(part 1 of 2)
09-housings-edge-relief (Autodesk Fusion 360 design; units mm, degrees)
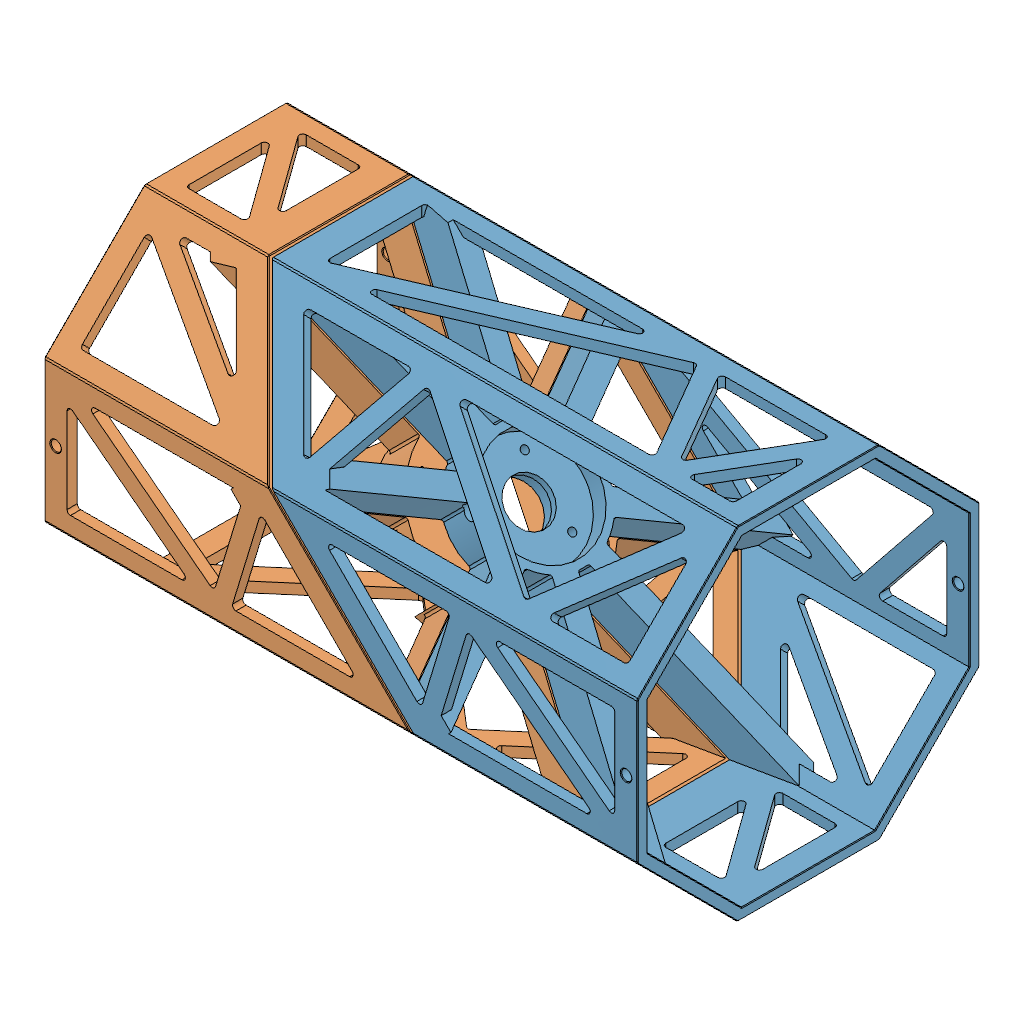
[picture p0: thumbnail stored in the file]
part number: 2026-11-02-20-17-55-344
part number: 2026-11-02-20-17-59-218
part number: 2026-11-02-20-17-59-224
parameter "bodyWidth" = 150 comment "Regular octagon across flats; corner diameter is larger."
parameter "bodyLength" = 260 comment "Overall straight length of the shared master blank."
parameter "splitAngle" = 45 comment "Keep this lesson angle at45 degrees."
parameter "faceGap" = 1 comment "Gap between the two printed joint faces."
parameter "wall" = 4.5 comment "Integrated shell and side brace radial thickness."
parameter "faceHalfWidth" = 31.066 (= "bodyWidth * ( sqrt(2) - 1 ) / 2") comment "Half-width of each outer planar facet."
parameter "memberWidth" = 8 comment "Nominal brace and corner chord width in a facet."
parameter "nodeHalfWidth" = 27.066 (= "faceHalfWidth - memberWidth / 2") comment "Chord centerlines measured from facet center."
parameter "jointNodeQ" = 7 comment "First truss skeleton row from the center joint plane."
parameter "endRim" = 10 comment "Uncut axial rim at each distant end."
parameter "endNodeX" = 124 (= "bodyLength / 2 - endRim + memberWidth / 2") comment "Last skeleton row before aperture inset."
parameter "apertureRadius" = 1.5 comment "Rounded internal corners at triangular openings."
parameter "spokeWidth" = 10 comment "Width of each deep bearing bulkhead spoke."
parameter "spokeDepth" = 18 comment "Bulkhead depth normal to the diagonal joint face."
parameter "carrierOD" = 52 comment "Outside of integrated A front bearing carrier."
parameter "rearCarrierClearance" = 46 comment "Internal carrier relief above front bearing shoulder."
parameter "tubeCornerChamfer" = 0.5 comment "Exposed outside octagon corner bevel."
parameter "tubeRimChamfer" = 0.3 comment "End rim and print-contact edge relief."
parameter "cordStation" = 125 (= "bodyLength / 2 - endRim / 2") comment "Load-test cord port center measured along body X."
parameter "bearingOD" = 22 comment "608 measured outside diameter."
parameter "bearingID" = 8 comment "608 bore."
parameter "bearingWidth" = 7 comment "608 width."
parameter "seatAllowance" = 0.2 comment "Trial DIAMETRAL clearance; choose with printed coupon."
parameter "seatDiameter" = 22.2 (= "bearingOD + seatAllowance") comment "Measured fit controls this."
parameter "coreOD" = 44 comment "Bearing holder outer diameter."
parameter "raceRelief" = 19.5 comment "Outer-ring shoulder opening; verify seals."
parameter "frontSeatDepth" = 7.1 comment "0.1 mm outer-ring axial allowance."
parameter "rearSeatDepth" = 7.2 comment "0.2 mm outer-ring axial float."
parameter "shoulder" = 3 comment "Backing behind each bearing seat."
parameter "supportSpacer" = 12 comment "Purchased metal M3 spacer length."
parameter "supportCircle" = 34 comment "Three M3 support bolts."
parameter "supportSpacerOD" = 6 comment "Purchased spacer outside diameter."
parameter "capThickness" = 3 comment "Both printed outer-ring retaining caps."
parameter "m3Clearance" = 3.3 comment "M3 through holes."
parameter "m4Clearance" = 4.3 comment "M4 through holes."
parameter "qFront" = 0.5 (= "faceGap / 2") comment "Front bearing starts at A mating face."
parameter "qFrontBack" = 10.6 (= "qFront + frontSeatDepth + shoulder") comment "End of integrated A holder."
parameter "qRearBase" = 22.6 (= "qFrontBack + supportSpacer") comment "Start of removable rear holder."
parameter "qRearBearing" = 25.6 (= "qRearBase + shoulder") comment "Rear bearing inner end."
parameter "qRearEnd" = 32.8 (= "qRearBearing + rearSeatDepth") comment "Rear holder outer end."
parameter "bearingSpacing" = 25.1 (= "qRearBearing - qFront") comment "Derived support-center spacing, not a bearing rating."
parameter "mountOD" = 76 comment "B mount and F flange outside diameter."
parameter "mountCircle" = 64 comment "Four M4 attachment holes."
parameter "mountOpening" = 50.3 comment "B through opening."
parameter "hubFace" = -23 comment "Metal hub flat mounting face."
parameter "adapterThickness" = 6 comment "F flange and metal compression sleeve length."
parameter "pilotDiameter" = 50 comment "F shallow centering pilot."
parameter "pilotInside" = 34 comment "Clearance around metal hub."
parameter "pilotHeight" = 2 comment "Short pilot only."
parameter "hubHoleSpacing" = 16 comment "Metal Sonic hub square hole spacing."
parameter "sleeveOD" = 8 comment "M4 metal compression sleeves."
parameter "sleeveAllowance" = 0.2 comment "Trial DIAMETRAL sleeve clearance."
parameter "shaftClearance" = 8.5 comment "F clearance hole; not a bearing."
parameter "nutAF" = 7.2 comment "M4 nominal 7 AF nut trial pocket."
parameter "nutDepth" = 4 comment "Open front M4 nut pocket."
parameter "rootRadius" = 1 comment "Hub-to-wall blend."
parameter "entryChamfer" = 0.4 comment "Assembly lead-in."
parameter "bedRelief" = 0.3 comment "Bed-contact edge allowance."
sketch "01 Master Octagon" plane through (0, 0, 0) normal (1, 0, 0) x axis (0, 0, -1)
  line L1 (31.066, 75) -> (75, 31.066)
  line L2 (-31.066, 75) -> (31.066, 75)
  line L3 (-75, 31.066) -> (-31.066, 75)
  line L4 (-75, -31.066) -> (-75, 31.066)
  line L5 (-31.066, -75) -> (-75, -31.066)
  line L6 (31.066, -75) -> (-31.066, -75)
  line L7 (75, -31.066) -> (31.066, -75)
  line L8 (75, 31.066) -> (75, -31.066)
  point P1 (0, 0)
  point P10 (0, 0)
  point P3 (31.066, 75)
  point P8 (31.066, -75)
  coincident P1 P10
  horizontal L2
  dimension "d59" distance P3 P8 = 150 (= "bodyWidth")
extrude "Extrude1" new body sketch "01 Master Octagon" distance 260 (= "bodyLength")
work_plane "WorkPlane1" RotateAngle 45 (= "splitAngle") ExtraOffset 0
split "Split1"
offset_faces "OffsetFaces1" distance -0.5 (= "-faceGap / 2")
offset_faces "OffsetFaces2" distance -0.5 (= "-faceGap / 2")
component_from_bodies "Body->Comp1"
component_from_bodies "Body->Comp2"
shell "Shell1" innerThickness 4.5 (= "wall")
shell "Shell1" innerThickness 4.5 (= "wall")
work_plane "WorkPlane1" RotateAngle -90 ExtraOffset 0
work_plane "WorkPlane2" AlongDistance 75 (= "bodyWidth / 2") ExtraOffset 0
sketch "A Facet 0 Triangle 1" plane through (0, 75, 0) normal (0, 1, 0) x axis (1, 0, 0)
  line L1 (-65.1005, -27.066) -> (-65.1005, 27.066)
  line L2 (60.9665, 27.066) -> (-65.1005, -27.066)
  line L3 (-65.1005, 27.066) -> (60.9665, 27.066)
  line L4 (-61.1005, -20.9953) -> (-61.1005, 23.066)
  line L5 (41.513, 23.066) -> (-61.1005, -20.9953)
  line L6 (-61.1005, 23.066) -> (41.513, 23.066)
  point P1 (0, 0)
  point P2 (-65.1005, 27.066)
  point P3 (-65.1005, -27.066)
  point P4 (60.9665, 27.066)
  dimension "d72" distance P1 P2 = 65.1005 (= "Linear Dimension-2")
  dimension "d73" distance P1 P2 = 27.066 (= "Linear Dimension-3")
  dimension "d74" distance P1 P3 = 65.1005 (= "Linear Dimension-4")
  dimension "d75" distance P1 P3 = 27.066 (= "Linear Dimension-5")
  dimension "d76" distance P1 P4 = 60.9665 (= "Linear Dimension-6")
  dimension "d77" distance P1 P4 = 27.066 (= "Linear Dimension-7")
  dimension "d78" = -4 (= "-memberWidth / 2")
extrude "Extrude1" cut sketch "A Facet 0 Triangle 1" profile of L5 L6 L4 against normal blind 4.7 (magnitude of "-( wall + 0.2 mm )")
sketch "A Facet 0 Triangle 2" plane through (0, 75, 0) normal (0, 1, 0) x axis (1, 0, 0)
  line L1 (60.9665, 27.066) -> (-65.1005, -27.066)
  line L2 (92.4832, -27.066) -> (60.9665, 27.066)
  line L3 (-65.1005, -27.066) -> (92.4832, -27.066)
  line L4 (59.2912, 21.9935) -> (-45.647, -23.066)
  line L5 (85.5258, -23.066) -> (59.2912, 21.9935)
  line L6 (-45.647, -23.066) -> (85.5258, -23.066)
  point P1 (0, 0)
  point P2 (-65.1005, -27.066)
  point P3 (60.9665, 27.066)
  point P4 (92.4832, -27.066)
  dimension "d81" distance P1 P2 = 65.1005 (= "Linear Dimension-2")
  dimension "d82" distance P1 P2 = 27.066 (= "Linear Dimension-3")
  dimension "d83" distance P1 P3 = 60.9665 (= "Linear Dimension-4")
  dimension "d84" distance P1 P3 = 27.066 (= "Linear Dimension-5")
  dimension "d85" distance P1 P4 = 92.4832 (= "Linear Dimension-6")
  dimension "d86" distance P1 P4 = 27.066 (= "Linear Dimension-7")
  dimension "d87" = 4 (= "memberWidth / 2")
extrude "Extrude2" cut sketch "A Facet 0 Triangle 2" profile of L5 L6 L4 against normal blind 4.7 (magnitude of "-( wall + 0.2 mm )")
sketch "A Facet 0 Triangle 3" plane through (0, 75, 0) normal (0, 1, 0) x axis (1, 0, 0)
  line L1 (92.4832, -27.066) -> (60.9665, 27.066)
  line L2 (124, 27.066) -> (92.4832, -27.066)
  line L3 (60.9665, 27.066) -> (124, 27.066)
  line L4 (92.4832, -19.1161) -> (67.924, 23.066)
  line L5 (117.0425, 23.066) -> (92.4832, -19.1161)
  line L6 (67.924, 23.066) -> (117.0425, 23.066)
  point P1 (0, 0)
  point P2 (60.9665, 27.066)
  point P3 (92.4832, -27.066)
  point P4 (124, 27.066)
  dimension "d90" distance P1 P2 = 60.9665 (= "Linear Dimension-2")
  dimension "d91" distance P1 P2 = 27.066 (= "Linear Dimension-3")
  dimension "d92" distance P1 P3 = 92.4832 (= "Linear Dimension-4")
  dimension "d93" distance P1 P3 = 27.066 (= "Linear Dimension-5")
  dimension "d94" distance P1 P4 = 124 (= "Linear Dimension-6")
  dimension "d95" distance P1 P4 = 27.066 (= "Linear Dimension-7")
  dimension "d96" = -4 (= "-memberWidth / 2")
extrude "Extrude3" cut sketch "A Facet 0 Triangle 3" profile of L5 L6 L4 against normal blind 4.7 (magnitude of "-( wall + 0.2 mm )")
sketch "A Facet 0 Triangle 4" plane through (0, 75, 0) normal (0, 1, 0) x axis (1, 0, 0)
  line L1 (124, 27.066) -> (92.4832, -27.066)
  line L2 (124, -27.066) -> (124, 27.066)
  line L3 (92.4832, -27.066) -> (124, -27.066)
  line L4 (120, 12.2459) -> (99.4407, -23.066)
  line L5 (120, -23.066) -> (120, 12.2459)
  line L6 (99.4407, -23.066) -> (120, -23.066)
  point P1 (0, 0)
  point P2 (92.4832, -27.066)
  point P3 (124, 27.066)
  point P4 (124, -27.066)
  dimension "d99" distance P1 P2 = 92.4832 (= "Linear Dimension-2")
  dimension "d100" distance P1 P2 = 27.066 (= "Linear Dimension-3")
  dimension "d101" distance P1 P3 = 124 (= "Linear Dimension-4")
  dimension "d102" distance P1 P3 = 27.066 (= "Linear Dimension-5")
  dimension "d103" distance P1 P4 = 124 (= "Linear Dimension-6")
  dimension "d104" distance P1 P4 = 27.066 (= "Linear Dimension-7")
  dimension "d105" = 4 (= "memberWidth / 2")
extrude "Extrude4" cut sketch "A Facet 0 Triangle 4" profile of L5 L6 L4 against normal blind 4.7 (magnitude of "-( wall + 0.2 mm )")
fillet "Fillet1" radius 1.5 (= "apertureRadius")
work_plane "WorkPlane3" RotateAngle -45 ExtraOffset 0
work_plane "WorkPlane4" AlongDistance 75 (= "bodyWidth / 2") ExtraOffset 0
sketch "A Facet 45 Triangle 1" plane through (0, 53.033, 53.033) normal (0, 0.7071, 0.7071) x axis (1, 0, 0)
  line L1 (-23.9949, -27.066) -> (-62.2721, 27.066)
  line L2 (-0.1814, 27.066) -> (-23.9949, -27.066)
  line L3 (-62.2721, 27.066) -> (-0.1814, 27.066)
  line L4 (-24.81, -18.9852) -> (-54.5447, 23.066)
  line L5 (-6.311, 23.066) -> (-24.81, -18.9852)
  line L6 (-54.5447, 23.066) -> (-6.311, 23.066)
  point P1 (0, 0)
  point P2 (-62.2721, 27.066)
  point P3 (-23.9949, -27.066)
  point P4 (-0.1814, 27.066)
  dimension "d114" distance P1 P2 = 62.2721 (= "Linear Dimension-2")
  dimension "d115" distance P1 P2 = 27.066 (= "Linear Dimension-3")
  dimension "d116" distance P1 P3 = 23.9949 (= "Linear Dimension-4")
  dimension "d117" distance P1 P3 = 27.066 (= "Linear Dimension-5")
  dimension "d118" distance P1 P4 = 0.1814 (= "Linear Dimension-6")
  dimension "d119" distance P1 P4 = 27.066 (= "Linear Dimension-7")
  dimension "d120" = -4 (= "-memberWidth / 2")
extrude "Extrude5" cut sketch "A Facet 45 Triangle 1" profile of L5 L6 L4 against normal blind 4.7 (magnitude of "-( wall + 0.2 mm )")
sketch "A Facet 45 Triangle 2" plane through (0, 53.033, 53.033) normal (0, 0.7071, 0.7071) x axis (1, 0, 0)
  line L1 (-0.1814, 27.066) -> (-23.9949, -27.066)
  line L2 (74.6684, -27.066) -> (-0.1814, 27.066)
  line L3 (-23.9949, -27.066) -> (74.6684, -27.066)
  line L4 (1.4863, 20.9235) -> (-17.8653, -23.066)
  line L5 (62.3117, -23.066) -> (1.4863, 20.9235)
  line L6 (-17.8653, -23.066) -> (62.3117, -23.066)
  point P1 (0, 0)
  point P2 (-23.9949, -27.066)
  point P3 (-0.1814, 27.066)
  point P4 (74.6684, -27.066)
  dimension "d123" distance P1 P2 = 23.9949 (= "Linear Dimension-2")
  dimension "d124" distance P1 P2 = 27.066 (= "Linear Dimension-3")
  dimension "d125" distance P1 P3 = 0.1814 (= "Linear Dimension-4")
  dimension "d126" distance P1 P3 = 27.066 (= "Linear Dimension-5")
  dimension "d127" distance P1 P4 = 74.6684 (= "Linear Dimension-6")
  dimension "d128" distance P1 P4 = 27.066 (= "Linear Dimension-7")
  dimension "d129" = 4 (= "memberWidth / 2")
extrude "Extrude6" cut sketch "A Facet 45 Triangle 2" profile of L5 L6 L4 against normal blind 4.7 (magnitude of "-( wall + 0.2 mm )")
sketch "A Facet 45 Triangle 3" plane through (0, 53.033, 53.033) normal (0, 0.7071, 0.7071) x axis (1, 0, 0)
  line L1 (74.6684, -27.066) -> (-0.1814, 27.066)
  line L2 (124, 27.066) -> (74.6684, -27.066)
  line L3 (-0.1814, 27.066) -> (124, 27.066)
  line L4 (74.1179, -21.7315) -> (12.1753, 23.066)
  line L5 (114.9429, 23.066) -> (74.1179, -21.7315)
  line L6 (12.1753, 23.066) -> (114.9429, 23.066)
  point P1 (0, 0)
  point P2 (-0.1814, 27.066)
  point P3 (74.6684, -27.066)
  point P4 (124, 27.066)
  dimension "d132" distance P1 P2 = 0.1814 (= "Linear Dimension-2")
  dimension "d133" distance P1 P2 = 27.066 (= "Linear Dimension-3")
  dimension "d134" distance P1 P3 = 74.6684 (= "Linear Dimension-4")
  dimension "d135" distance P1 P3 = 27.066 (= "Linear Dimension-5")
  dimension "d136" distance P1 P4 = 124 (= "Linear Dimension-6")
  dimension "d137" distance P1 P4 = 27.066 (= "Linear Dimension-7")
  dimension "d138" = -4 (= "-memberWidth / 2")
extrude "Extrude7" cut sketch "A Facet 45 Triangle 3" profile of L5 L6 L4 against normal blind 4.7 (magnitude of "-( wall + 0.2 mm )")
sketch "A Facet 45 Triangle 4" plane through (0, 53.033, 53.033) normal (0, 0.7071, 0.7071) x axis (1, 0, 0)
  line L1 (124, 27.066) -> (74.6684, -27.066)
  line L2 (124, -27.066) -> (124, 27.066)
  line L3 (74.6684, -27.066) -> (124, -27.066)
  line L4 (120, 16.7383) -> (83.7255, -23.066)
  line L5 (120, -23.066) -> (120, 16.7383)
  line L6 (83.7255, -23.066) -> (120, -23.066)
  point P1 (0, 0)
  point P2 (74.6684, -27.066)
  point P3 (124, 27.066)
  point P4 (124, -27.066)
  dimension "d141" distance P1 P2 = 74.6684 (= "Linear Dimension-2")
  dimension "d142" distance P1 P2 = 27.066 (= "Linear Dimension-3")
  dimension "d143" distance P1 P3 = 124 (= "Linear Dimension-4")
  dimension "d144" distance P1 P3 = 27.066 (= "Linear Dimension-5")
  dimension "d145" distance P1 P4 = 124 (= "Linear Dimension-6")
  dimension "d146" distance P1 P4 = 27.066 (= "Linear Dimension-7")
  dimension "d147" = 4 (= "memberWidth / 2")
extrude "Extrude8" cut sketch "A Facet 45 Triangle 4" profile of L5 L6 L4 against normal blind 4.7 (magnitude of "-( wall + 0.2 mm )")
fillet "Fillet2" radius 1.5 (= "apertureRadius")
work_plane "WorkPlane5" RotateAngle 0 ExtraOffset 0
work_plane "WorkPlane6" AlongDistance 75 (= "bodyWidth / 2") ExtraOffset 0
sketch "A Facet 90 Triangle 1" plane through (0, 0, 75) normal (0, 0, 1) x axis (1, 0, 0)
  line L1 (36.9655, -27.066) -> (-17.1665, 27.066)
  line L2 (53.4167, 27.066) -> (36.9655, -27.066)
  line L3 (-17.1665, 27.066) -> (53.4167, 27.066)
  line L4 (35.0777, -19.5214) -> (-7.5097, 23.066)
  line L5 (48.0205, 23.066) -> (35.0777, -19.5214)
  line L6 (-7.5097, 23.066) -> (48.0205, 23.066)
  point P1 (0, 0)
  point P2 (-17.1665, 27.066)
  point P3 (36.9655, -27.066)
  point P4 (53.4167, 27.066)
  dimension "d156" distance P1 P2 = 17.1665 (= "Linear Dimension-2")
  dimension "d157" distance P1 P2 = 27.066 (= "Linear Dimension-3")
  dimension "d158" distance P1 P3 = 36.9655 (= "Linear Dimension-4")
  dimension "d159" distance P1 P3 = 27.066 (= "Linear Dimension-5")
  dimension "d160" distance P1 P4 = 53.4167 (= "Linear Dimension-6")
  dimension "d161" distance P1 P4 = 27.066 (= "Linear Dimension-7")
  dimension "d162" = -4 (= "-memberWidth / 2")
extrude "Extrude9" cut sketch "A Facet 90 Triangle 1" profile of L5 L6 L4 against normal blind 4.7 (magnitude of "-( wall + 0.2 mm )")
sketch "A Facet 90 Triangle 2" plane through (0, 0, 75) normal (0, 0, 1) x axis (1, 0, 0)
  line L1 (53.4167, 27.066) -> (36.9655, -27.066)
  line L2 (124, -27.066) -> (53.4167, 27.066)
  line L3 (36.9655, -27.066) -> (124, -27.066)
  line L4 (55.5648, 20.3777) -> (42.3618, -23.066)
  line L5 (112.2115, -23.066) -> (55.5648, 20.3777)
  line L6 (42.3618, -23.066) -> (112.2115, -23.066)
  point P1 (0, 0)
  point P2 (36.9655, -27.066)
  point P3 (53.4167, 27.066)
  point P4 (124, -27.066)
  dimension "d165" distance P1 P2 = 36.9655 (= "Linear Dimension-2")
  dimension "d166" distance P1 P2 = 27.066 (= "Linear Dimension-3")
  dimension "d167" distance P1 P3 = 53.4167 (= "Linear Dimension-4")
  dimension "d168" distance P1 P3 = 27.066 (= "Linear Dimension-5")
  dimension "d169" distance P1 P4 = 124 (= "Linear Dimension-6")
  dimension "d170" distance P1 P4 = 27.066 (= "Linear Dimension-7")
  dimension "d171" = 4 (= "memberWidth / 2")
extrude "Extrude10" cut sketch "A Facet 90 Triangle 2" profile of L5 L6 L4 against normal blind 4.7 (magnitude of "-( wall + 0.2 mm )")
sketch "A Facet 90 Triangle 3" plane through (0, 0, 75) normal (0, 0, 1) x axis (1, 0, 0)
  line L1 (124, -27.066) -> (53.4167, 27.066)
  line L2 (124, 27.066) -> (124, -27.066)
  line L3 (53.4167, 27.066) -> (124, 27.066)
  line L4 (120, -18.9574) -> (65.2053, 23.066)
  line L5 (120, 23.066) -> (120, -18.9574)
  line L6 (65.2053, 23.066) -> (120, 23.066)
  point P1 (0, 0)
  point P2 (53.4167, 27.066)
  point P3 (124, -27.066)
  point P4 (124, 27.066)
  dimension "d174" distance P1 P2 = 53.4167 (= "Linear Dimension-2")
  dimension "d175" distance P1 P2 = 27.066 (= "Linear Dimension-3")
  dimension "d176" distance P1 P3 = 124 (= "Linear Dimension-4")
  dimension "d177" distance P1 P3 = 27.066 (= "Linear Dimension-5")
  dimension "d178" distance P1 P4 = 124 (= "Linear Dimension-6")
  dimension "d179" distance P1 P4 = 27.066 (= "Linear Dimension-7")
  dimension "d180" = -4 (= "-memberWidth / 2")
extrude "Extrude11" cut sketch "A Facet 90 Triangle 3" profile of L5 L6 L4 against normal blind 4.7 (magnitude of "-( wall + 0.2 mm )")
fillet "Fillet3" radius 1.5 (= "apertureRadius")
work_plane "WorkPlane7" RotateAngle 45 ExtraOffset 0
work_plane "WorkPlane8" AlongDistance 75 (= "bodyWidth / 2") ExtraOffset 0
sketch "A Facet 135 Triangle 1" plane through (0, -53.033, 53.033) normal (0, -0.7071, 0.7071) x axis (1, 0, 0)
  line L1 (82.0711, -27.066) -> (43.7939, 27.066)
  line L2 (124, 27.066) -> (82.0711, -27.066)
  line L3 (43.7939, 27.066) -> (124, 27.066)
  line L4 (82.2175, -20.3449) -> (51.5213, 23.066)
  line L5 (115.8422, 23.066) -> (82.2175, -20.3449)
  line L6 (51.5213, 23.066) -> (115.8422, 23.066)
  point P1 (0, 0)
  point P2 (43.7939, 27.066)
  point P3 (82.0711, -27.066)
  point P4 (124, 27.066)
  dimension "d189" distance P1 P2 = 43.7939 (= "Linear Dimension-2")
  dimension "d190" distance P1 P2 = 27.066 (= "Linear Dimension-3")
  dimension "d191" distance P1 P3 = 82.0711 (= "Linear Dimension-4")
  dimension "d192" distance P1 P3 = 27.066 (= "Linear Dimension-5")
  dimension "d193" distance P1 P4 = 124 (= "Linear Dimension-6")
  dimension "d194" distance P1 P4 = 27.066 (= "Linear Dimension-7")
  dimension "d195" = -4 (= "-memberWidth / 2")
extrude "Extrude12" cut sketch "A Facet 135 Triangle 1" profile of L5 L6 L4 against normal blind 4.7 (magnitude of "-( wall + 0.2 mm )")
sketch "A Facet 135 Triangle 2" plane through (0, -53.033, 53.033) normal (0, -0.7071, 0.7071) x axis (1, 0, 0)
  line L1 (124, 27.066) -> (82.0711, -27.066)
  line L2 (124, -27.066) -> (124, 27.066)
  line L3 (82.0711, -27.066) -> (124, -27.066)
  line L4 (120, 15.3697) -> (90.2289, -23.066)
  line L5 (120, -23.066) -> (120, 15.3697)
  line L6 (90.2289, -23.066) -> (120, -23.066)
  point P1 (0, 0)
  point P2 (82.0711, -27.066)
  point P3 (124, 27.066)
  point P4 (124, -27.066)
  dimension "d198" distance P1 P2 = 82.0711 (= "Linear Dimension-2")
  dimension "d199" distance P1 P2 = 27.066 (= "Linear Dimension-3")
  dimension "d200" distance P1 P3 = 124 (= "Linear Dimension-4")
  dimension "d201" distance P1 P3 = 27.066 (= "Linear Dimension-5")
  dimension "d202" distance P1 P4 = 124 (= "Linear Dimension-6")
  dimension "d203" distance P1 P4 = 27.066 (= "Linear Dimension-7")
  dimension "d204" = 4 (= "memberWidth / 2")
extrude "Extrude13" cut sketch "A Facet 135 Triangle 2" profile of L5 L6 L4 against normal blind 4.7 (magnitude of "-( wall + 0.2 mm )")
fillet "Fillet4" radius 1.5 (= "apertureRadius")
work_plane "WorkPlane9" RotateAngle 90 ExtraOffset 0
work_plane "WorkPlane10" AlongDistance 75 (= "bodyWidth / 2") ExtraOffset 0
sketch "A Facet 180 Triangle 1" plane through (0, -75, 0) normal (0, -1, 0) x axis (-1, 0, 0)
  line L1 (-84.8995, 27.066) -> (-84.8995, -27.066)
  line L2 (-124, -27.066) -> (-84.8995, 27.066)
  line L3 (-84.8995, -27.066) -> (-124, -27.066)
  line L4 (-88.8995, 14.697) -> (-88.8995, -23.066)
  line L5 (-116.1764, -23.066) -> (-88.8995, 14.697)
  line L6 (-88.8995, -23.066) -> (-116.1764, -23.066)
  point P1 (0, 0)
  point P2 (-84.8995, -27.066)
  point P3 (-84.8995, 27.066)
  point P4 (-124, -27.066)
  dimension "d213" distance P1 P2 = 84.8995 (= "Linear Dimension-2")
  dimension "d214" distance P1 P2 = 27.066 (= "Linear Dimension-3")
  dimension "d215" distance P1 P3 = 84.8995 (= "Linear Dimension-4")
  dimension "d216" distance P1 P3 = 27.066 (= "Linear Dimension-5")
  dimension "d217" distance P1 P4 = 124 (= "Linear Dimension-6")
  dimension "d218" distance P1 P4 = 27.066 (= "Linear Dimension-7")
  dimension "d219" = -4 (= "-memberWidth / 2")
extrude "Extrude14" cut sketch "A Facet 180 Triangle 1" profile of L5 L6 L4 against normal blind 4.7 (magnitude of "-( wall + 0.2 mm )")
sketch "A Facet 180 Triangle 2" plane through (0, -75, 0) normal (0, -1, 0) x axis (-1, 0, 0)
  line L1 (-124, -27.066) -> (-84.8995, 27.066)
  line L2 (-124, 27.066) -> (-124, -27.066)
  line L3 (-84.8995, 27.066) -> (-124, 27.066)
  line L4 (-120, -14.697) -> (-92.7231, 23.066)
  line L5 (-120, 23.066) -> (-120, -14.697)
  line L6 (-92.7231, 23.066) -> (-120, 23.066)
  point P1 (0, 0)
  point P2 (-84.8995, 27.066)
  point P3 (-124, -27.066)
  point P4 (-124, 27.066)
  dimension "d222" distance P1 P2 = 84.8995 (= "Linear Dimension-2")
  dimension "d223" distance P1 P2 = 27.066 (= "Linear Dimension-3")
  dimension "d224" distance P1 P3 = 124 (= "Linear Dimension-4")
  dimension "d225" distance P1 P3 = 27.066 (= "Linear Dimension-5")
  dimension "d226" distance P1 P4 = 124 (= "Linear Dimension-6")
  dimension "d227" distance P1 P4 = 27.066 (= "Linear Dimension-7")
  dimension "d228" = 4 (= "memberWidth / 2")
extrude "Extrude15" cut sketch "A Facet 180 Triangle 2" profile of L5 L6 L4 against normal blind 4.7 (magnitude of "-( wall + 0.2 mm )")
fillet "Fillet5" radius 1.5 (= "apertureRadius")
work_plane "WorkPlane11" RotateAngle 135 ExtraOffset 0
work_plane "WorkPlane12" AlongDistance 75 (= "bodyWidth / 2") ExtraOffset 0
sketch "A Facet 225 Triangle 1" plane through (0, -53.033, -53.033) normal (0, -0.7071, -0.7071) x axis (1, 0, 0)
  line L1 (43.7939, -27.066) -> (82.0711, 27.066)
  line L2 (124, 27.066) -> (43.7939, -27.066)
  line L3 (82.0711, 27.066) -> (124, 27.066)
  line L4 (59.6927, -11.51) -> (84.1416, 23.066)
  line L5 (110.9231, 23.066) -> (59.6927, -11.51)
  line L6 (84.1416, 23.066) -> (110.9231, 23.066)
  point P1 (0, 0)
  point P2 (82.0711, 27.066)
  point P3 (43.7939, -27.066)
  point P4 (124, 27.066)
  dimension "d237" distance P1 P2 = 82.0711 (= "Linear Dimension-2")
  dimension "d238" distance P1 P2 = 27.066 (= "Linear Dimension-3")
  dimension "d239" distance P1 P3 = 43.7939 (= "Linear Dimension-4")
  dimension "d240" distance P1 P3 = 27.066 (= "Linear Dimension-5")
  dimension "d241" distance P1 P4 = 124 (= "Linear Dimension-6")
  dimension "d242" distance P1 P4 = 27.066 (= "Linear Dimension-7")
  dimension "d243" = -4 (= "-memberWidth / 2")
extrude "Extrude16" cut sketch "A Facet 225 Triangle 1" profile of L5 L6 L4 against normal blind 4.7 (magnitude of "-( wall + 0.2 mm )")
sketch "A Facet 225 Triangle 2" plane through (0, -53.033, -53.033) normal (0, -0.7071, -0.7071) x axis (1, 0, 0)
  line L1 (124, 27.066) -> (43.7939, -27.066)
  line L2 (124, -27.066) -> (124, 27.066)
  line L3 (43.7939, -27.066) -> (124, -27.066)
  line L4 (120, 19.5406) -> (56.8709, -23.066)
  line L5 (120, -23.066) -> (120, 19.5406)
  line L6 (56.8709, -23.066) -> (120, -23.066)
  point P1 (0, 0)
  point P2 (43.7939, -27.066)
  point P3 (124, 27.066)
  point P4 (124, -27.066)
  dimension "d246" distance P1 P2 = 43.7939 (= "Linear Dimension-2")
  dimension "d247" distance P1 P2 = 27.066 (= "Linear Dimension-3")
  dimension "d248" distance P1 P3 = 124 (= "Linear Dimension-4")
  dimension "d249" distance P1 P3 = 27.066 (= "Linear Dimension-5")
  dimension "d250" distance P1 P4 = 124 (= "Linear Dimension-6")
  dimension "d251" distance P1 P4 = 27.066 (= "Linear Dimension-7")
  dimension "d252" = 4 (= "memberWidth / 2")
extrude "Extrude17" cut sketch "A Facet 225 Triangle 2" profile of L5 L6 L4 against normal blind 4.7 (magnitude of "-( wall + 0.2 mm )")
fillet "Fillet6" radius 1.5 (= "apertureRadius")
work_plane "WorkPlane13" RotateAngle 180 ExtraOffset 0
work_plane "WorkPlane14" AlongDistance 75 (= "bodyWidth / 2") ExtraOffset 0
sketch "A Facet 270 Triangle 1" plane through (0, 0, -75) normal (0, 0, -1) x axis (-1, 0, 0)
  line L1 (17.1665, 27.066) -> (-36.9655, -27.066)
  line L2 (-80.4828, -27.066) -> (17.1665, 27.066)
  line L3 (-36.9655, -27.066) -> (-80.4828, -27.066)
  line L4 (-5.7896, 9.7668) -> (-38.6224, -23.066)
  line L5 (-65.0169, -23.066) -> (-5.7896, 9.7668)
  line L6 (-38.6224, -23.066) -> (-65.0169, -23.066)
  point P1 (0, 0)
  point P2 (-36.9655, -27.066)
  point P3 (17.1665, 27.066)
  point P4 (-80.4828, -27.066)
  dimension "d261" distance P1 P2 = 36.9655 (= "Linear Dimension-2")
  dimension "d262" distance P1 P2 = 27.066 (= "Linear Dimension-3")
  dimension "d263" distance P1 P3 = 17.1665 (= "Linear Dimension-4")
  dimension "d264" distance P1 P3 = 27.066 (= "Linear Dimension-5")
  dimension "d265" distance P1 P4 = 80.4828 (= "Linear Dimension-6")
  dimension "d266" distance P1 P4 = 27.066 (= "Linear Dimension-7")
  dimension "d267" = -4 (= "-memberWidth / 2")
extrude "Extrude18" cut sketch "A Facet 270 Triangle 1" profile of L5 L6 L4 against normal blind 4.7 (magnitude of "-( wall + 0.2 mm )")
sketch "A Facet 270 Triangle 2" plane through (0, 0, -75) normal (0, 0, -1) x axis (-1, 0, 0)
  line L1 (-80.4828, -27.066) -> (17.1665, 27.066)
  line L2 (-124, 27.066) -> (-80.4828, -27.066)
  line L3 (17.1665, 27.066) -> (-124, 27.066)
  line L4 (-79.4759, -21.9343) -> (1.7007, 23.066)
  line L5 (-115.6521, 23.066) -> (-79.4759, -21.9343)
  line L6 (1.7007, 23.066) -> (-115.6521, 23.066)
  point P1 (0, 0)
  point P2 (17.1665, 27.066)
  point P3 (-80.4828, -27.066)
  point P4 (-124, 27.066)
  dimension "d270" distance P1 P2 = 17.1665 (= "Linear Dimension-2")
  dimension "d271" distance P1 P2 = 27.066 (= "Linear Dimension-3")
  dimension "d272" distance P1 P3 = 80.4828 (= "Linear Dimension-4")
  dimension "d273" distance P1 P3 = 27.066 (= "Linear Dimension-5")
  dimension "d274" distance P1 P4 = 124 (= "Linear Dimension-6")
  dimension "d275" distance P1 P4 = 27.066 (= "Linear Dimension-7")
  dimension "d276" = 4 (= "memberWidth / 2")
extrude "Extrude19" cut sketch "A Facet 270 Triangle 2" profile of L5 L6 L4 against normal blind 4.7 (magnitude of "-( wall + 0.2 mm )")
sketch "A Facet 270 Triangle 3" plane through (0, 0, -75) normal (0, 0, -1) x axis (-1, 0, 0)
  line L1 (-124, 27.066) -> (-80.4828, -27.066)
  line L2 (-124, -27.066) -> (-124, 27.066)
  line L3 (-80.4828, -27.066) -> (-124, -27.066)
  line L4 (-120, 15.7062) -> (-88.8307, -23.066)
  line L5 (-120, -23.066) -> (-120, 15.7062)
  line L6 (-88.8307, -23.066) -> (-120, -23.066)
  point P1 (0, 0)
  point P2 (-80.4828, -27.066)
  point P3 (-124, 27.066)
  point P4 (-124, -27.066)
  dimension "d279" distance P1 P2 = 80.4828 (= "Linear Dimension-2")
  dimension "d280" distance P1 P2 = 27.066 (= "Linear Dimension-3")
  dimension "d281" distance P1 P3 = 124 (= "Linear Dimension-4")
  dimension "d282" distance P1 P3 = 27.066 (= "Linear Dimension-5")
  dimension "d283" distance P1 P4 = 124 (= "Linear Dimension-6")
  dimension "d284" distance P1 P4 = 27.066 (= "Linear Dimension-7")
  dimension "d285" = -4 (= "-memberWidth / 2")
extrude "Extrude20" cut sketch "A Facet 270 Triangle 3" profile of L5 L6 L4 against normal blind 4.7 (magnitude of "-( wall + 0.2 mm )")
fillet "Fillet7" radius 1.5 (= "apertureRadius")
work_plane "WorkPlane15" RotateAngle 225 ExtraOffset 0
work_plane "WorkPlane16" AlongDistance 75 (= "bodyWidth / 2") ExtraOffset 0
sketch "A Facet 315 Triangle 1" plane through (0, 53.033, -53.033) normal (0, 0.7071, -0.7071) x axis (1, 0, 0)
  line L1 (-62.2721, -27.066) -> (-23.9949, 27.066)
  line L2 (25.3367, 27.066) -> (-62.2721, -27.066)
  line L3 (-23.9949, 27.066) -> (25.3367, 27.066)
  line L4 (-47.6674, -13.34) -> (-21.9244, 23.066)
  line L5 (11.2532, 23.066) -> (-47.6674, -13.34)
  line L6 (-21.9244, 23.066) -> (11.2532, 23.066)
  point P1 (0, 0)
  point P2 (-23.9949, 27.066)
  point P3 (-62.2721, -27.066)
  point P4 (25.3367, 27.066)
  dimension "d294" distance P1 P2 = 23.9949 (= "Linear Dimension-2")
  dimension "d295" distance P1 P2 = 27.066 (= "Linear Dimension-3")
  dimension "d296" distance P1 P3 = 62.2721 (= "Linear Dimension-4")
  dimension "d297" distance P1 P3 = 27.066 (= "Linear Dimension-5")
  dimension "d298" distance P1 P4 = 25.3367 (= "Linear Dimension-6")
  dimension "d299" distance P1 P4 = 27.066 (= "Linear Dimension-7")
  dimension "d300" = -4 (= "-memberWidth / 2")
extrude "Extrude21" cut sketch "A Facet 315 Triangle 1" profile of L5 L6 L4 against normal blind 4.7 (magnitude of "-( wall + 0.2 mm )")
sketch "A Facet 315 Triangle 2" plane through (0, 53.033, -53.033) normal (0, 0.7071, -0.7071) x axis (1, 0, 0)
  line L1 (25.3367, 27.066) -> (-62.2721, -27.066)
  line L2 (61.9093, -27.066) -> (25.3367, 27.066)
  line L3 (-62.2721, -27.066) -> (61.9093, -27.066)
  line L4 (24.1722, 21.6445) -> (-48.1886, -23.066)
  line L5 (54.3795, -23.066) -> (24.1722, 21.6445)
  line L6 (-48.1886, -23.066) -> (54.3795, -23.066)
  point P1 (0, 0)
  point P2 (-62.2721, -27.066)
  point P3 (25.3367, 27.066)
  point P4 (61.9093, -27.066)
  dimension "d303" distance P1 P2 = 62.2721 (= "Linear Dimension-2")
  dimension "d304" distance P1 P2 = 27.066 (= "Linear Dimension-3")
  dimension "d305" distance P1 P3 = 25.3367 (= "Linear Dimension-4")
  dimension "d306" distance P1 P3 = 27.066 (= "Linear Dimension-5")
  dimension "d307" distance P1 P4 = 61.9093 (= "Linear Dimension-6")
  dimension "d308" distance P1 P4 = 27.066 (= "Linear Dimension-7")
  dimension "d309" = 4 (= "memberWidth / 2")
extrude "Extrude22" cut sketch "A Facet 315 Triangle 2" profile of L5 L6 L4 against normal blind 4.7 (magnitude of "-( wall + 0.2 mm )")
sketch "A Facet 315 Triangle 3" plane through (0, 53.033, -53.033) normal (0, 0.7071, -0.7071) x axis (1, 0, 0)
  line L1 (61.9093, -27.066) -> (25.3367, 27.066)
  line L2 (124, 27.066) -> (61.9093, -27.066)
  line L3 (25.3367, 27.066) -> (124, 27.066)
  line L4 (62.6909, -21.0779) -> (32.8665, 23.066)
  line L5 (113.325, 23.066) -> (62.6909, -21.0779)
  line L6 (32.8665, 23.066) -> (113.325, 23.066)
  point P1 (0, 0)
  point P2 (25.3367, 27.066)
  point P3 (61.9093, -27.066)
  point P4 (124, 27.066)
  dimension "d312" distance P1 P2 = 25.3367 (= "Linear Dimension-2")
  dimension "d313" distance P1 P2 = 27.066 (= "Linear Dimension-3")
  dimension "d314" distance P1 P3 = 61.9093 (= "Linear Dimension-4")
  dimension "d315" distance P1 P3 = 27.066 (= "Linear Dimension-5")
  dimension "d316" distance P1 P4 = 124 (= "Linear Dimension-6")
  dimension "d317" distance P1 P4 = 27.066 (= "Linear Dimension-7")
  dimension "d318" = -4 (= "-memberWidth / 2")
extrude "Extrude23" cut sketch "A Facet 315 Triangle 3" profile of L5 L6 L4 against normal blind 4.7 (magnitude of "-( wall + 0.2 mm )")
sketch "A Facet 315 Triangle 4" plane through (0, 53.033, -53.033) normal (0, 0.7071, -0.7071) x axis (1, 0, 0)
  line L1 (124, 27.066) -> (61.9093, -27.066)
  line L2 (124, -27.066) -> (124, 27.066)
  line L3 (61.9093, -27.066) -> (124, -27.066)
  line L4 (120, 18.272) -> (72.5843, -23.066)
  line L5 (120, -23.066) -> (120, 18.272)
  line L6 (72.5843, -23.066) -> (120, -23.066)
  point P1 (0, 0)
  point P2 (61.9093, -27.066)
  point P3 (124, 27.066)
  point P4 (124, -27.066)
  dimension "d321" distance P1 P2 = 61.9093 (= "Linear Dimension-2")
  dimension "d322" distance P1 P2 = 27.066 (= "Linear Dimension-3")
  dimension "d323" distance P1 P3 = 124 (= "Linear Dimension-4")
  dimension "d324" distance P1 P3 = 27.066 (= "Linear Dimension-5")
  dimension "d325" distance P1 P4 = 124 (= "Linear Dimension-6")
  dimension "d326" distance P1 P4 = 27.066 (= "Linear Dimension-7")
  dimension "d327" = 4 (= "memberWidth / 2")
extrude "Extrude24" cut sketch "A Facet 315 Triangle 4" profile of L5 L6 L4 against normal blind 4.7 (magnitude of "-( wall + 0.2 mm )")
fillet "Fillet8" radius 1.5 (= "apertureRadius")
work_plane "WorkPlane1" RotateAngle -90 ExtraOffset 0
work_plane "WorkPlane2" AlongDistance 75 (= "bodyWidth / 2") ExtraOffset 0
sketch "B Facet 0 Triangle 1" plane through (0, 75, 0) normal (0, 1, 0) x axis (1, 0, 0)
  line L1 (-84.8995, -27.066) -> (-84.8995, 27.066)
  line L2 (-124, 27.066) -> (-84.8995, -27.066)
  line L3 (-84.8995, 27.066) -> (-124, 27.066)
  line L4 (-88.8995, -14.697) -> (-88.8995, 23.066)
  line L5 (-116.1764, 23.066) -> (-88.8995, -14.697)
  line L6 (-88.8995, 23.066) -> (-116.1764, 23.066)
  point P1 (0, 0)
  point P2 (-84.8995, 27.066)
  point P3 (-84.8995, -27.066)
  point P4 (-124, 27.066)
  dimension "d336" distance P1 P2 = 84.8995 (= "Linear Dimension-2")
  dimension "d337" distance P1 P2 = 27.066 (= "Linear Dimension-3")
  dimension "d338" distance P1 P3 = 84.8995 (= "Linear Dimension-4")
  dimension "d339" distance P1 P3 = 27.066 (= "Linear Dimension-5")
  dimension "d340" distance P1 P4 = 124 (= "Linear Dimension-6")
  dimension "d341" distance P1 P4 = 27.066 (= "Linear Dimension-7")
  dimension "d342" = 4 (= "memberWidth / 2")
extrude "Extrude1" cut sketch "B Facet 0 Triangle 1" profile of L5 L6 L4 against normal blind 4.7 (magnitude of "-( wall + 0.2 mm )")
sketch "B Facet 0 Triangle 2" plane through (0, 75, 0) normal (0, 1, 0) x axis (1, 0, 0)
  line L1 (-124, 27.066) -> (-84.8995, -27.066)
  line L2 (-124, -27.066) -> (-124, 27.066)
  line L3 (-84.8995, -27.066) -> (-124, -27.066)
  line L4 (-120, 14.697) -> (-92.7231, -23.066)
  line L5 (-120, -23.066) -> (-120, 14.697)
  line L6 (-92.7231, -23.066) -> (-120, -23.066)
  point P1 (0, 0)
  point P2 (-84.8995, -27.066)
  point P3 (-124, 27.066)
  point P4 (-124, -27.066)
  dimension "d345" distance P1 P2 = 84.8995 (= "Linear Dimension-2")
  dimension "d346" distance P1 P2 = 27.066 (= "Linear Dimension-3")
  dimension "d347" distance P1 P3 = 124 (= "Linear Dimension-4")
  dimension "d348" distance P1 P3 = 27.066 (= "Linear Dimension-5")
  dimension "d349" distance P1 P4 = 124 (= "Linear Dimension-6")
  dimension "d350" distance P1 P4 = 27.066 (= "Linear Dimension-7")
  dimension "d351" = -4 (= "-memberWidth / 2")
extrude "Extrude2" cut sketch "B Facet 0 Triangle 2" profile of L5 L6 L4 against normal blind 4.7 (magnitude of "-( wall + 0.2 mm )")
fillet "Fillet1" radius 1.5 (= "apertureRadius")
work_plane "WorkPlane3" RotateAngle -45 ExtraOffset 0
work_plane "WorkPlane4" AlongDistance 75 (= "bodyWidth / 2") ExtraOffset 0
sketch "B Facet 45 Triangle 1" plane through (0, 53.033, 53.033) normal (0, 0.7071, 0.7071) x axis (1, 0, 0)
  line L1 (-43.7939, -27.066) -> (-82.0711, 27.066)
  line L2 (-124, 27.066) -> (-43.7939, -27.066)
  line L3 (-82.0711, 27.066) -> (-124, 27.066)
  line L4 (-59.6927, -11.51) -> (-84.1416, 23.066)
  line L5 (-110.9231, 23.066) -> (-59.6927, -11.51)
  line L6 (-84.1416, 23.066) -> (-110.9231, 23.066)
  point P1 (0, 0)
  point P2 (-82.0711, 27.066)
  point P3 (-43.7939, -27.066)
  point P4 (-124, 27.066)
  dimension "d360" distance P1 P2 = 82.0711 (= "Linear Dimension-2")
  dimension "d361" distance P1 P2 = 27.066 (= "Linear Dimension-3")
  dimension "d362" distance P1 P3 = 43.7939 (= "Linear Dimension-4")
  dimension "d363" distance P1 P3 = 27.066 (= "Linear Dimension-5")
  dimension "d364" distance P1 P4 = 124 (= "Linear Dimension-6")
  dimension "d365" distance P1 P4 = 27.066 (= "Linear Dimension-7")
  dimension "d366" = 4 (= "memberWidth / 2")
extrude "Extrude3" cut sketch "B Facet 45 Triangle 1" profile of L5 L6 L4 against normal blind 4.7 (magnitude of "-( wall + 0.2 mm )")
sketch "B Facet 45 Triangle 2" plane through (0, 53.033, 53.033) normal (0, 0.7071, 0.7071) x axis (1, 0, 0)
  line L1 (-124, 27.066) -> (-43.7939, -27.066)
  line L2 (-124, -27.066) -> (-124, 27.066)
  line L3 (-43.7939, -27.066) -> (-124, -27.066)
  line L4 (-120, 19.5406) -> (-56.8709, -23.066)
  line L5 (-120, -23.066) -> (-120, 19.5406)
  line L6 (-56.8709, -23.066) -> (-120, -23.066)
  point P1 (0, 0)
  point P2 (-43.7939, -27.066)
  point P3 (-124, 27.066)
  point P4 (-124, -27.066)
  dimension "d369" distance P1 P2 = 43.7939 (= "Linear Dimension-2")
  dimension "d370" distance P1 P2 = 27.066 (= "Linear Dimension-3")
  dimension "d371" distance P1 P3 = 124 (= "Linear Dimension-4")
  dimension "d372" distance P1 P3 = 27.066 (= "Linear Dimension-5")
  dimension "d373" distance P1 P4 = 124 (= "Linear Dimension-6")
  dimension "d374" distance P1 P4 = 27.066 (= "Linear Dimension-7")
  dimension "d375" = -4 (= "-memberWidth / 2")
extrude "Extrude4" cut sketch "B Facet 45 Triangle 2" profile of L5 L6 L4 against normal blind 4.7 (magnitude of "-( wall + 0.2 mm )")
fillet "Fillet2" radius 1.5 (= "apertureRadius")
work_plane "WorkPlane5" RotateAngle 0 ExtraOffset 0
work_plane "WorkPlane6" AlongDistance 75 (= "bodyWidth / 2") ExtraOffset 0
sketch "B Facet 90 Triangle 1" plane through (0, 0, 75) normal (0, 0, 1) x axis (1, 0, 0)
  line L1 (-36.9655, 27.066) -> (17.1665, -27.066)
  line L2 (-53.4167, -27.066) -> (-36.9655, 27.066)
  line L3 (17.1665, -27.066) -> (-53.4167, -27.066)
  line L4 (-35.0777, 19.5214) -> (7.5097, -23.066)
  line L5 (-48.0205, -23.066) -> (-35.0777, 19.5214)
  line L6 (7.5097, -23.066) -> (-48.0205, -23.066)
  point P1 (0, 0)
  point P2 (17.1665, -27.066)
  point P3 (-36.9655, 27.066)
  point P4 (-53.4167, -27.066)
  dimension "d384" distance P1 P2 = 17.1665 (= "Linear Dimension-2")
  dimension "d385" distance P1 P2 = 27.066 (= "Linear Dimension-3")
  dimension "d386" distance P1 P3 = 36.9655 (= "Linear Dimension-4")
  dimension "d387" distance P1 P3 = 27.066 (= "Linear Dimension-5")
  dimension "d388" distance P1 P4 = 53.4167 (= "Linear Dimension-6")
  dimension "d389" distance P1 P4 = 27.066 (= "Linear Dimension-7")
  dimension "d390" = -4 (= "-memberWidth / 2")
extrude "Extrude5" cut sketch "B Facet 90 Triangle 1" profile of L5 L6 L4 against normal blind 4.7 (magnitude of "-( wall + 0.2 mm )")
sketch "B Facet 90 Triangle 2" plane through (0, 0, 75) normal (0, 0, 1) x axis (1, 0, 0)
  line L1 (-53.4167, -27.066) -> (-36.9655, 27.066)
  line L2 (-124, 27.066) -> (-53.4167, -27.066)
  line L3 (-36.9655, 27.066) -> (-124, 27.066)
  line L4 (-55.5648, -20.3777) -> (-42.3618, 23.066)
  line L5 (-112.2115, 23.066) -> (-55.5648, -20.3777)
  line L6 (-42.3618, 23.066) -> (-112.2115, 23.066)
  point P1 (0, 0)
  point P2 (-36.9655, 27.066)
  point P3 (-53.4167, -27.066)
  point P4 (-124, 27.066)
  dimension "d393" distance P1 P2 = 36.9655 (= "Linear Dimension-2")
  dimension "d394" distance P1 P2 = 27.066 (= "Linear Dimension-3")
  dimension "d395" distance P1 P3 = 53.4167 (= "Linear Dimension-4")
  dimension "d396" distance P1 P3 = 27.066 (= "Linear Dimension-5")
  dimension "d397" distance P1 P4 = 124 (= "Linear Dimension-6")
  dimension "d398" distance P1 P4 = 27.066 (= "Linear Dimension-7")
  dimension "d399" = 4 (= "memberWidth / 2")
extrude "Extrude6" cut sketch "B Facet 90 Triangle 2" profile of L5 L6 L4 against normal blind 4.7 (magnitude of "-( wall + 0.2 mm )")
sketch "B Facet 90 Triangle 3" plane through (0, 0, 75) normal (0, 0, 1) x axis (1, 0, 0)
  line L1 (-124, 27.066) -> (-53.4167, -27.066)
  line L2 (-124, -27.066) -> (-124, 27.066)
  line L3 (-53.4167, -27.066) -> (-124, -27.066)
  line L4 (-120, 18.9574) -> (-65.2053, -23.066)
  line L5 (-120, -23.066) -> (-120, 18.9574)
  line L6 (-65.2053, -23.066) -> (-120, -23.066)
  point P1 (0, 0)
  point P2 (-53.4167, -27.066)
  point P3 (-124, 27.066)
  point P4 (-124, -27.066)
  dimension "d402" distance P1 P2 = 53.4167 (= "Linear Dimension-2")
  dimension "d403" distance P1 P2 = 27.066 (= "Linear Dimension-3")
  dimension "d404" distance P1 P3 = 124 (= "Linear Dimension-4")
  dimension "d405" distance P1 P3 = 27.066 (= "Linear Dimension-5")
  dimension "d406" distance P1 P4 = 124 (= "Linear Dimension-6")
  dimension "d407" distance P1 P4 = 27.066 (= "Linear Dimension-7")
  dimension "d408" = -4 (= "-memberWidth / 2")
extrude "Extrude7" cut sketch "B Facet 90 Triangle 3" profile of L5 L6 L4 against normal blind 4.7 (magnitude of "-( wall + 0.2 mm )")
fillet "Fillet3" radius 1.5 (= "apertureRadius")
work_plane "WorkPlane7" RotateAngle 45 ExtraOffset 0
work_plane "WorkPlane8" AlongDistance 75 (= "bodyWidth / 2") ExtraOffset 0
sketch "B Facet 135 Triangle 1" plane through (0, -53.033, 53.033) normal (0, -0.7071, 0.7071) x axis (1, 0, 0)
  line L1 (62.2721, -27.066) -> (23.9949, 27.066)
  line L2 (-25.3367, 27.066) -> (62.2721, -27.066)
  line L3 (23.9949, 27.066) -> (-25.3367, 27.066)
  line L4 (47.6674, -13.34) -> (21.9244, 23.066)
  line L5 (-11.2532, 23.066) -> (47.6674, -13.34)
  line L6 (21.9244, 23.066) -> (-11.2532, 23.066)
  point P1 (0, 0)
  point P2 (23.9949, 27.066)
  point P3 (62.2721, -27.066)
  point P4 (-25.3367, 27.066)
  dimension "d417" distance P1 P2 = 23.9949 (= "Linear Dimension-2")
  dimension "d418" distance P1 P2 = 27.066 (= "Linear Dimension-3")
  dimension "d419" distance P1 P3 = 62.2721 (= "Linear Dimension-4")
  dimension "d420" distance P1 P3 = 27.066 (= "Linear Dimension-5")
  dimension "d421" distance P1 P4 = 25.3367 (= "Linear Dimension-6")
  dimension "d422" distance P1 P4 = 27.066 (= "Linear Dimension-7")
  dimension "d423" = 4 (= "memberWidth / 2")
extrude "Extrude8" cut sketch "B Facet 135 Triangle 1" profile of L5 L6 L4 against normal blind 4.7 (magnitude of "-( wall + 0.2 mm )")
sketch "B Facet 135 Triangle 2" plane through (0, -53.033, 53.033) normal (0, -0.7071, 0.7071) x axis (1, 0, 0)
  line L1 (-25.3367, 27.066) -> (62.2721, -27.066)
  line L2 (-61.9093, -27.066) -> (-25.3367, 27.066)
  line L3 (62.2721, -27.066) -> (-61.9093, -27.066)
  line L4 (-24.1722, 21.6445) -> (48.1886, -23.066)
  line L5 (-54.3795, -23.066) -> (-24.1722, 21.6445)
  line L6 (48.1886, -23.066) -> (-54.3795, -23.066)
  point P1 (0, 0)
  point P2 (62.2721, -27.066)
  point P3 (-25.3367, 27.066)
  point P4 (-61.9093, -27.066)
  dimension "d426" distance P1 P2 = 62.2721 (= "Linear Dimension-2")
  dimension "d427" distance P1 P2 = 27.066 (= "Linear Dimension-3")
  dimension "d428" distance P1 P3 = 25.3367 (= "Linear Dimension-4")
  dimension "d429" distance P1 P3 = 27.066 (= "Linear Dimension-5")
  dimension "d430" distance P1 P4 = 61.9093 (= "Linear Dimension-6")
  dimension "d431" distance P1 P4 = 27.066 (= "Linear Dimension-7")
  dimension "d432" = -4 (= "-memberWidth / 2")
extrude "Extrude9" cut sketch "B Facet 135 Triangle 2" profile of L5 L6 L4 against normal blind 4.7 (magnitude of "-( wall + 0.2 mm )")
sketch "B Facet 135 Triangle 3" plane through (0, -53.033, 53.033) normal (0, -0.7071, 0.7071) x axis (1, 0, 0)
  line L1 (-61.9093, -27.066) -> (-25.3367, 27.066)
  line L2 (-124, 27.066) -> (-61.9093, -27.066)
  line L3 (-25.3367, 27.066) -> (-124, 27.066)
  line L4 (-62.6909, -21.0779) -> (-32.8665, 23.066)
  line L5 (-113.325, 23.066) -> (-62.6909, -21.0779)
  line L6 (-32.8665, 23.066) -> (-113.325, 23.066)
  point P1 (0, 0)
  point P2 (-25.3367, 27.066)
  point P3 (-61.9093, -27.066)
  point P4 (-124, 27.066)
  dimension "d435" distance P1 P2 = 25.3367 (= "Linear Dimension-2")
  dimension "d436" distance P1 P2 = 27.066 (= "Linear Dimension-3")
  dimension "d437" distance P1 P3 = 61.9093 (= "Linear Dimension-4")
  dimension "d438" distance P1 P3 = 27.066 (= "Linear Dimension-5")
  dimension "d439" distance P1 P4 = 124 (= "Linear Dimension-6")
  dimension "d440" distance P1 P4 = 27.066 (= "Linear Dimension-7")
  dimension "d441" = 4 (= "memberWidth / 2")
extrude "Extrude10" cut sketch "B Facet 135 Triangle 3" profile of L5 L6 L4 against normal blind 4.7 (magnitude of "-( wall + 0.2 mm )")
sketch "B Facet 135 Triangle 4" plane through (0, -53.033, 53.033) normal (0, -0.7071, 0.7071) x axis (1, 0, 0)
  line L1 (-124, 27.066) -> (-61.9093, -27.066)
  line L2 (-124, -27.066) -> (-124, 27.066)
  line L3 (-61.9093, -27.066) -> (-124, -27.066)
  line L4 (-120, 18.272) -> (-72.5843, -23.066)
  line L5 (-120, -23.066) -> (-120, 18.272)
  line L6 (-72.5843, -23.066) -> (-120, -23.066)
  point P1 (0, 0)
  point P2 (-61.9093, -27.066)
  point P3 (-124, 27.066)
  point P4 (-124, -27.066)
  dimension "d444" distance P1 P2 = 61.9093 (= "Linear Dimension-2")
  dimension "d445" distance P1 P2 = 27.066 (= "Linear Dimension-3")
  dimension "d446" distance P1 P3 = 124 (= "Linear Dimension-4")
  dimension "d447" distance P1 P3 = 27.066 (= "Linear Dimension-5")
  dimension "d448" distance P1 P4 = 124 (= "Linear Dimension-6")
  dimension "d449" distance P1 P4 = 27.066 (= "Linear Dimension-7")
  dimension "d450" = -4 (= "-memberWidth / 2")
extrude "Extrude11" cut sketch "B Facet 135 Triangle 4" profile of L5 L6 L4 against normal blind 4.7 (magnitude of "-( wall + 0.2 mm )")
fillet "Fillet4" radius 1.5 (= "apertureRadius")
work_plane "WorkPlane9" RotateAngle 90 ExtraOffset 0
work_plane "WorkPlane10" AlongDistance 75 (= "bodyWidth / 2") ExtraOffset 0
sketch "B Facet 180 Triangle 1" plane through (0, -75, 0) normal (0, -1, 0) x axis (-1, 0, 0)
  line L1 (-65.1005, 27.066) -> (-65.1005, -27.066)
  line L2 (-2.067, -27.066) -> (-65.1005, 27.066)
  line L3 (-65.1005, -27.066) -> (-2.067, -27.066)
  line L4 (-61.1005, 18.3583) -> (-61.1005, -23.066)
  line L5 (-12.8644, -23.066) -> (-61.1005, 18.3583)
  line L6 (-61.1005, -23.066) -> (-12.8644, -23.066)
  point P1 (0, 0)
  point P2 (-65.1005, -27.066)
  point P3 (-65.1005, 27.066)
  point P4 (-2.067, -27.066)
  dimension "d459" distance P1 P2 = 65.1005 (= "Linear Dimension-2")
  dimension "d460" distance P1 P2 = 27.066 (= "Linear Dimension-3")
  dimension "d461" distance P1 P3 = 65.1005 (= "Linear Dimension-4")
  dimension "d462" distance P1 P3 = 27.066 (= "Linear Dimension-5")
  dimension "d463" distance P1 P4 = 2.067 (= "Linear Dimension-6")
  dimension "d464" distance P1 P4 = 27.066 (= "Linear Dimension-7")
  dimension "d465" = 4 (= "memberWidth / 2")
extrude "Extrude12" cut sketch "B Facet 180 Triangle 1" profile of L5 L6 L4 against normal blind 4.7 (magnitude of "-( wall + 0.2 mm )")
sketch "B Facet 180 Triangle 2" plane through (0, -75, 0) normal (0, -1, 0) x axis (-1, 0, 0)
  line L1 (-2.067, -27.066) -> (-65.1005, 27.066)
  line L2 (60.9665, 27.066) -> (-2.067, -27.066)
  line L3 (-65.1005, 27.066) -> (60.9665, 27.066)
  line L4 (-2.067, -21.7934) -> (-54.3031, 23.066)
  line L5 (50.1691, 23.066) -> (-2.067, -21.7934)
  line L6 (-54.3031, 23.066) -> (50.1691, 23.066)
  point P1 (0, 0)
  point P2 (-65.1005, 27.066)
  point P3 (-2.067, -27.066)
  point P4 (60.9665, 27.066)
  dimension "d468" distance P1 P2 = 65.1005 (= "Linear Dimension-2")
  dimension "d469" distance P1 P2 = 27.066 (= "Linear Dimension-3")
  dimension "d470" distance P1 P3 = 2.067 (= "Linear Dimension-4")
  dimension "d471" distance P1 P3 = 27.066 (= "Linear Dimension-5")
  dimension "d472" distance P1 P4 = 60.9665 (= "Linear Dimension-6")
  dimension "d473" distance P1 P4 = 27.066 (= "Linear Dimension-7")
  dimension "d474" = -4 (= "-memberWidth / 2")
extrude "Extrude13" cut sketch "B Facet 180 Triangle 2" profile of L5 L6 L4 against normal blind 4.7 (magnitude of "-( wall + 0.2 mm )")
sketch "B Facet 180 Triangle 3" plane through (0, -75, 0) normal (0, -1, 0) x axis (-1, 0, 0)
  line L1 (60.9665, 27.066) -> (-2.067, -27.066)
  line L2 (124, -27.066) -> (60.9665, 27.066)
  line L3 (-2.067, -27.066) -> (124, -27.066)
  line L4 (60.9665, 21.7934) -> (8.7304, -23.066)
  line L5 (113.2026, -23.066) -> (60.9665, 21.7934)
  line L6 (8.7304, -23.066) -> (113.2026, -23.066)
  point P1 (0, 0)
  point P2 (-2.067, -27.066)
  point P3 (60.9665, 27.066)
  point P4 (124, -27.066)
  dimension "d477" distance P1 P2 = 2.067 (= "Linear Dimension-2")
  dimension "d478" distance P1 P2 = 27.066 (= "Linear Dimension-3")
  dimension "d479" distance P1 P3 = 60.9665 (= "Linear Dimension-4")
  dimension "d480" distance P1 P3 = 27.066 (= "Linear Dimension-5")
  dimension "d481" distance P1 P4 = 124 (= "Linear Dimension-6")
  dimension "d482" distance P1 P4 = 27.066 (= "Linear Dimension-7")
  dimension "d483" = 4 (= "memberWidth / 2")
extrude "Extrude14" cut sketch "B Facet 180 Triangle 3" profile of L5 L6 L4 against normal blind 4.7 (magnitude of "-( wall + 0.2 mm )")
